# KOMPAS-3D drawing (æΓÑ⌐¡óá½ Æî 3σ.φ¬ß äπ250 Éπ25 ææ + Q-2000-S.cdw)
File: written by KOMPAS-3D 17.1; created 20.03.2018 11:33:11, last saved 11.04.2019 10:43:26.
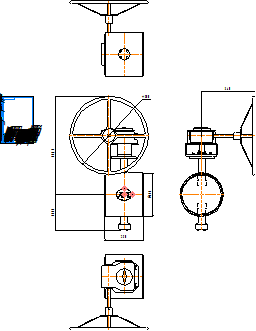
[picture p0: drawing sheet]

Sheet 1: A4, portrait

Title block, sheet 1: name: Стейнвал ТМ 3х.экс / Ду250 Ру25 СС + Q-2000-S; material: Внимание! Данный продукт является объектом авторского права ООО «Торговый Дом АДЛ». / Запрещается изменение, копирование, распространение / (в том числе путем копирования на другие сайты и ресурсы в Интернете) / или любое иное использование информации и объектов без предварительного / согласия правообладателя (ООО «Торговый Дом АДЛ»).; mass: 97,3; sheets: 1; organisation: ООО "Торговый дом АДЛ"; sheet format: A4; stored path: \\adlc.lan\data\АДЛ_ПКД\3D-модели\ADL production\Дисковые поворотные затворы СТЕЙНВАЛ\Трехэксцентриковый\Стейнвал c-c\С редуктором\KOMPAS 2D\Стейнвал ТМ 3х.экс Ду250 Ру25 СС + Q-2000-S.cdw

Views: Вид 1, Проекционный вид 4
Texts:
  kka
  adl
Dimensions and other numbers on the sheet: 500; 250; 226,3; 624,5; 273; 1:1; 1; 97,3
